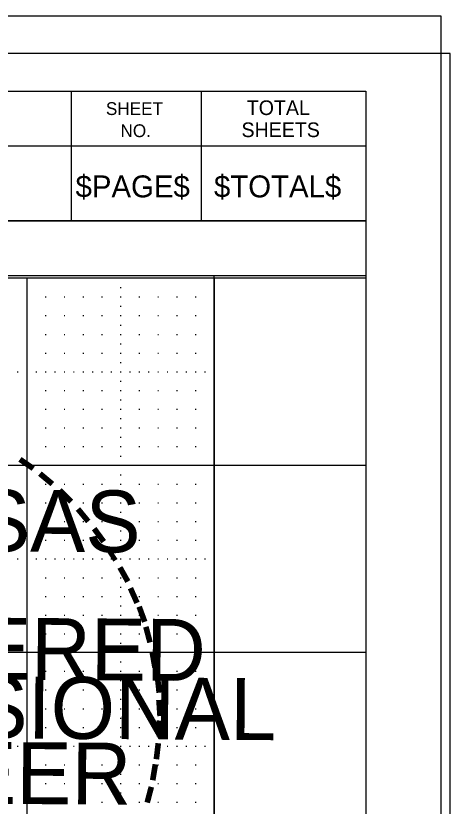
# Model space of a CAD drawing. Extents: x -3.6 to 32.1, y -0.4 to 25.6.
# Drawn here: x 29.748 to 32.067, y 16.724 to 20.947 of the extents above; entities that cross this region are included whole.
import ezdxf

# ---------------------------------------------------------------- set-up
doc = ezdxf.new("R2010")
doc.units = 0
for name, color, linetype in [('Level 1', 7, 'Continuous'), ('Level 4', 7, 'Continuous'), ('Level 5', 7, 'Continuous'), ('Level 62', 7, 'Continuous'), ('Level 63', 7, 'Continuous'), ('Level 63 Full', 7, 'Continuous'), ('R_Border Prelim', 7, 'Continuous'), ('R_Border Prem', 7, 'Continuous')]:
    doc.layers.add(name, color=color, linetype=linetype)

msp = doc.modelspace()

# ---------------------------------------------------------------- linework, layer by layer
at = {"layer": 'Level 1'}
for p, q in [((30.043, 20.5449), (30.043, 19.8509)), ((30.737, 20.5449), (30.737, 19.8509)), ((31.617, 20.2509), (27.307, 20.2509)), ((31.617, 20.2529), (31.617, 20.2529)), ((31.617, 19.8509), (27.307, 19.8509)), ((27.603, 19.8509), (31.617, 19.8509)), ((31.617, 19.5569), (25.353, 19.5569))]:
    msp.add_line(p, q, dxfattribs=at)
at = {"layer": 'Level 4'}
for p, q in [((31.617, 19.545), (-0.001, 19.545)), ((29.808, 0.545), (29.808, 19.545)), ((30.808, 0.545), (30.808, 19.545)), ((31.617, 18.545), (-0.001, 18.545)), ((31.617, 17.545), (-0.001, 17.545))]:
    msp.add_line(p, q, dxfattribs=at)
at = {"layer": 'Level 5'}
for p, q in [((30.3055, 19.495), (30.3105, 19.495)), ((29.9055, 19.445), (29.9105, 19.445)), ((30.0055, 19.445), (30.0105, 19.445)), ((30.1055, 19.445), (30.1105, 19.445)), ((30.2055, 19.445), (30.2105, 19.445)), ((30.3055, 19.445), (30.3105, 19.445)), ((30.4055, 19.445), (30.4105, 19.445)), ((30.5055, 19.445), (30.5105, 19.445)), ((30.6055, 19.445), (30.6105, 19.445)), ((30.7055, 19.445), (30.7105, 19.445)), ((30.3055, 19.395), (30.3105, 19.395)), ((29.9055, 19.345), (29.9105, 19.345)), ((30.0055, 19.345), (30.0105, 19.345)), ((30.1055, 19.345), (30.1105, 19.345)), ((30.2055, 19.345), (30.2105, 19.345)), ((30.3055, 19.345), (30.3105, 19.345)), ((30.4055, 19.345), (30.4105, 19.345)), ((30.5055, 19.345), (30.5105, 19.345)), ((30.6055, 19.345), (30.6105, 19.345)), ((30.7055, 19.345), (30.7105, 19.345)), ((30.3055, 19.295), (30.3105, 19.295)), ((29.9055, 19.245), (29.9105, 19.245)), ((30.0055, 19.245), (30.0105, 19.245)), ((30.1055, 19.245), (30.1105, 19.245)), ((30.2055, 19.245), (30.2105, 19.245)), ((30.3055, 19.245), (30.3105, 19.245)), ((30.4055, 19.245), (30.4105, 19.245)), ((30.5055, 19.245), (30.5105, 19.245)), ((30.6055, 19.245), (30.6105, 19.245)), ((30.7055, 19.245), (30.7105, 19.245)), ((30.3055, 19.195), (30.3105, 19.195)), ((29.9055, 19.145), (29.9105, 19.145)), ((30.0055, 19.145), (30.0105, 19.145)), ((30.1055, 19.145), (30.1105, 19.145)), ((30.2055, 19.145), (30.2105, 19.145)), ((30.3055, 19.145), (30.3105, 19.145)), ((30.4055, 19.145), (30.4105, 19.145)), ((30.5055, 19.145), (30.5105, 19.145)), ((30.6055, 19.145), (30.6105, 19.145)), ((30.7055, 19.145), (30.7105, 19.145)), ((30.3055, 19.095), (30.3105, 19.095)), ((29.7555, 19.045), (29.7605, 19.045)), ((29.8555, 19.045), (29.8605, 19.045)), ((29.9055, 19.045), (29.9105, 19.045)), ((29.9555, 19.045), (29.9605, 19.045)), ((30.0055, 19.045), (30.0105, 19.045)), ((30.0555, 19.045), (30.0605, 19.045)), ((30.1055, 19.045), (30.1105, 19.045)), ((30.1555, 19.045), (30.1605, 19.045)), ((30.2055, 19.045), (30.2105, 19.045)), ((30.2555, 19.045), (30.2605, 19.045)), ((30.3055, 19.045), (30.3105, 19.045)), ((30.3555, 19.045), (30.3605, 19.045)), ((30.4055, 19.045), (30.4105, 19.045)), ((30.4555, 19.045), (30.4605, 19.045)), ((30.5055, 19.045), (30.5105, 19.045)), ((30.5555, 19.045), (30.5605, 19.045)), ((30.6055, 19.045), (30.6105, 19.045)), ((30.6555, 19.045), (30.6605, 19.045)), ((30.7055, 19.045), (30.7105, 19.045)), ((30.7555, 19.045), (30.7605, 19.045)), ((30.3055, 18.995), (30.3105, 18.995)), ((29.9055, 18.945), (29.9105, 18.945)), ((30.0055, 18.945), (30.0105, 18.945)), ((30.1055, 18.945), (30.1105, 18.945)), ((30.2055, 18.945), (30.2105, 18.945)), ((30.3055, 18.945), (30.3105, 18.945)), ((30.4055, 18.945), (30.4105, 18.945)), ((30.5055, 18.945), (30.5105, 18.945)), ((30.6055, 18.945), (30.6105, 18.945)), ((30.7055, 18.945), (30.7105, 18.945)), ((30.3055, 18.895), (30.3105, 18.895)), ((29.9055, 18.845), (29.9105, 18.845)), ((30.0055, 18.845), (30.0105, 18.845)), ((30.1055, 18.845), (30.1105, 18.845)), ((30.2055, 18.845), (30.2105, 18.845)), ((30.3055, 18.845), (30.3105, 18.845)), ((30.4055, 18.845), (30.4105, 18.845)), ((30.5055, 18.845), (30.5105, 18.845)), ((30.6055, 18.845), (30.6105, 18.845)), ((30.7055, 18.845), (30.7105, 18.845)), ((30.3055, 18.795), (30.3105, 18.795)), ((29.9055, 18.745), (29.9105, 18.745)), ((30.0055, 18.745), (30.0105, 18.745)), ((30.1055, 18.745), (30.1105, 18.745)), ((30.2055, 18.745), (30.2105, 18.745)), ((30.3055, 18.745), (30.3105, 18.745)), ((30.4055, 18.745), (30.4105, 18.745)), ((30.5055, 18.745), (30.5105, 18.745)), ((30.6055, 18.745), (30.6105, 18.745)), ((30.7055, 18.745), (30.7105, 18.745)), ((30.3055, 18.695), (30.3105, 18.695)), ((29.9055, 18.645), (29.9105, 18.645)), ((30.0055, 18.645), (30.0105, 18.645)), ((30.1055, 18.645), (30.1105, 18.645)), ((30.2055, 18.645), (30.2105, 18.645)), ((30.3055, 18.645), (30.3105, 18.645)), ((30.4055, 18.645), (30.4105, 18.645)), ((30.5055, 18.645), (30.5105, 18.645)), ((30.6055, 18.645), (30.6105, 18.645)), ((30.7055, 18.645), (30.7105, 18.645)), ((30.3055, 18.595), (30.3105, 18.595)), ((30.3055, 18.495), (30.3105, 18.495)), ((29.9055, 18.445), (29.9105, 18.445)), ((30.0055, 18.445), (30.0105, 18.445)), ((30.1055, 18.445), (30.1105, 18.445)), ((30.2055, 18.445), (30.2105, 18.445)), ((30.3055, 18.445), (30.3105, 18.445)), ((30.4055, 18.445), (30.4105, 18.445)), ((30.5055, 18.445), (30.5105, 18.445)), ((30.6055, 18.445), (30.6105, 18.445)), ((30.7055, 18.445), (30.7105, 18.445)), ((30.3055, 18.395), (30.3105, 18.395)), ((29.9055, 18.345), (29.9105, 18.345)), ((30.0055, 18.345), (30.0105, 18.345)), ((30.1055, 18.345), (30.1105, 18.345)), ((30.2055, 18.345), (30.2105, 18.345)), ((30.3055, 18.345), (30.3105, 18.345)), ((30.4055, 18.345), (30.4105, 18.345)), ((30.5055, 18.345), (30.5105, 18.345)), ((30.6055, 18.345), (30.6105, 18.345)), ((30.7055, 18.345), (30.7105, 18.345)), ((30.3055, 18.295), (30.3105, 18.295)), ((29.9055, 18.245), (29.9105, 18.245)), ((30.0055, 18.245), (30.0105, 18.245)), ((30.1055, 18.245), (30.1105, 18.245)), ((30.2055, 18.245), (30.2105, 18.245)), ((30.3055, 18.245), (30.3105, 18.245)), ((30.4055, 18.245), (30.4105, 18.245)), ((30.5055, 18.245), (30.5105, 18.245)), ((30.6055, 18.245), (30.6105, 18.245)), ((30.7055, 18.245), (30.7105, 18.245)), ((30.3055, 18.195), (30.3105, 18.195)), ((29.9055, 18.145), (29.9105, 18.145)), ((30.0055, 18.145), (30.0105, 18.145)), ((30.1055, 18.145), (30.1105, 18.145)), ((30.2055, 18.145), (30.2105, 18.145)), ((30.3055, 18.145), (30.3105, 18.145)), ((30.4055, 18.145), (30.4105, 18.145)), ((30.5055, 18.145), (30.5105, 18.145)), ((30.6055, 18.145), (30.6105, 18.145)), ((30.7055, 18.145), (30.7105, 18.145)), ((30.3055, 18.095), (30.3105, 18.095)), ((29.7555, 18.045), (29.7605, 18.045)), ((29.8555, 18.045), (29.8605, 18.045)), ((29.9055, 18.045), (29.9105, 18.045)), ((29.9555, 18.045), (29.9605, 18.045)), ((30.0055, 18.045), (30.0105, 18.045)), ((30.0555, 18.045), (30.0605, 18.045)), ((30.1055, 18.045), (30.1105, 18.045)), ((30.1555, 18.045), (30.1605, 18.045)), ((30.2055, 18.045), (30.2105, 18.045)), ((30.2555, 18.045), (30.2605, 18.045)), ((30.3055, 18.045), (30.3105, 18.045)), ((30.3555, 18.045), (30.3605, 18.045)), ((30.4055, 18.045), (30.4105, 18.045)), ((30.4555, 18.045), (30.4605, 18.045)), ((30.5055, 18.045), (30.5105, 18.045)), ((30.5555, 18.045), (30.5605, 18.045)), ((30.6055, 18.045), (30.6105, 18.045)), ((30.6555, 18.045), (30.6605, 18.045)), ((30.7055, 18.045), (30.7105, 18.045)), ((30.7555, 18.045), (30.7605, 18.045)), ((30.3055, 17.995), (30.3105, 17.995)), ((29.9055, 17.945), (29.9105, 17.945)), ((30.0055, 17.945), (30.0105, 17.945)), ((30.1055, 17.945), (30.1105, 17.945)), ((30.2055, 17.945), (30.2105, 17.945)), ((30.3055, 17.945), (30.3105, 17.945)), ((30.4055, 17.945), (30.4105, 17.945)), ((30.5055, 17.945), (30.5105, 17.945)), ((30.6055, 17.945), (30.6105, 17.945)), ((30.7055, 17.945), (30.7105, 17.945)), ((30.3055, 17.895), (30.3105, 17.895)), ((29.9055, 17.845), (29.9105, 17.845)), ((30.0055, 17.845), (30.0105, 17.845)), ((30.1055, 17.845), (30.1105, 17.845)), ((30.2055, 17.845), (30.2105, 17.845)), ((30.3055, 17.845), (30.3105, 17.845)), ((30.4055, 17.845), (30.4105, 17.845)), ((30.5055, 17.845), (30.5105, 17.845)), ((30.6055, 17.845), (30.6105, 17.845)), ((30.7055, 17.845), (30.7105, 17.845)), ((30.3055, 17.795), (30.3105, 17.795)), ((29.9055, 17.745), (29.9105, 17.745)), ((30.0055, 17.745), (30.0105, 17.745)), ((30.1055, 17.745), (30.1105, 17.745)), ((30.2055, 17.745), (30.2105, 17.745)), ((30.3055, 17.745), (30.3105, 17.745)), ((30.4055, 17.745), (30.4105, 17.745)), ((30.5055, 17.745), (30.5105, 17.745)), ((30.6055, 17.745), (30.6105, 17.745)), ((30.7055, 17.745), (30.7105, 17.745)), ((30.3055, 17.695), (30.3105, 17.695)), ((29.9055, 17.645), (29.9105, 17.645)), ((30.0055, 17.645), (30.0105, 17.645)), ((30.1055, 17.645), (30.1105, 17.645)), ((30.2055, 17.645), (30.2105, 17.645)), ((30.3055, 17.645), (30.3105, 17.645)), ((30.4055, 17.645), (30.4105, 17.645)), ((30.5055, 17.645), (30.5105, 17.645)), ((30.6055, 17.645), (30.6105, 17.645)), ((30.7055, 17.645), (30.7105, 17.645)), ((30.3055, 17.595), (30.3105, 17.595)), ((30.3055, 17.495), (30.3105, 17.495)), ((29.9055, 17.445), (29.9105, 17.445)), ((30.0055, 17.445), (30.0105, 17.445)), ((30.1055, 17.445), (30.1105, 17.445)), ((30.2055, 17.445), (30.2105, 17.445)), ((30.3055, 17.445), (30.3105, 17.445)), ((30.4055, 17.445), (30.4105, 17.445)), ((30.5055, 17.445), (30.5105, 17.445)), ((30.6055, 17.445), (30.6105, 17.445)), ((30.7055, 17.445), (30.7105, 17.445)), ((30.3055, 17.395), (30.3105, 17.395)), ((29.9055, 17.345), (29.9105, 17.345)), ((30.0055, 17.345), (30.0105, 17.345)), ((30.1055, 17.345), (30.1105, 17.345)), ((30.2055, 17.345), (30.2105, 17.345)), ((30.3055, 17.345), (30.3105, 17.345)), ((30.4055, 17.345), (30.4105, 17.345)), ((30.5055, 17.345), (30.5105, 17.345)), ((30.6055, 17.345), (30.6105, 17.345)), ((30.7055, 17.345), (30.7105, 17.345)), ((30.3055, 17.295), (30.3105, 17.295)), ((29.9055, 17.245), (29.9105, 17.245)), ((30.0055, 17.245), (30.0105, 17.245)), ((30.1055, 17.245), (30.1105, 17.245)), ((30.2055, 17.245), (30.2105, 17.245)), ((30.3055, 17.245), (30.3105, 17.245)), ((30.4055, 17.245), (30.4105, 17.245)), ((30.5055, 17.245), (30.5105, 17.245)), ((30.6055, 17.245), (30.6105, 17.245)), ((30.7055, 17.245), (30.7105, 17.245)), ((30.3055, 17.195), (30.3105, 17.195)), ((29.9055, 17.145), (29.9105, 17.145)), ((30.0055, 17.145), (30.0105, 17.145)), ((30.1055, 17.145), (30.1105, 17.145)), ((30.2055, 17.145), (30.2105, 17.145)), ((30.3055, 17.145), (30.3105, 17.145)), ((30.4055, 17.145), (30.4105, 17.145)), ((30.5055, 17.145), (30.5105, 17.145)), ((30.6055, 17.145), (30.6105, 17.145)), ((30.7055, 17.145), (30.7105, 17.145)), ((30.3055, 17.095), (30.3105, 17.095)), ((29.7555, 17.045), (29.7605, 17.045)), ((29.8555, 17.045), (29.8605, 17.045)), ((29.9055, 17.045), (29.9105, 17.045)), ((29.9555, 17.045), (29.9605, 17.045)), ((30.0055, 17.045), (30.0105, 17.045)), ((30.0555, 17.045), (30.0605, 17.045)), ((30.1055, 17.045), (30.1105, 17.045)), ((30.1555, 17.045), (30.1605, 17.045)), ((30.2055, 17.045), (30.2105, 17.045)), ((30.2555, 17.045), (30.2605, 17.045)), ((30.3055, 17.045), (30.3105, 17.045)), ((30.3555, 17.045), (30.3605, 17.045)), ((30.4055, 17.045), (30.4105, 17.045)), ((30.4555, 17.045), (30.4605, 17.045)), ((30.5055, 17.045), (30.5105, 17.045)), ((30.5555, 17.045), (30.5605, 17.045)), ((30.6055, 17.045), (30.6105, 17.045)), ((30.6555, 17.045), (30.6605, 17.045)), ((30.7055, 17.045), (30.7105, 17.045)), ((30.7555, 17.045), (30.7605, 17.045)), ((30.3055, 16.995), (30.3105, 16.995)), ((29.9055, 16.945), (29.9105, 16.945)), ((30.0055, 16.945), (30.0105, 16.945)), ((30.1055, 16.945), (30.1105, 16.945)), ((30.2055, 16.945), (30.2105, 16.945)), ((30.3055, 16.945), (30.3105, 16.945)), ((30.4055, 16.945), (30.4105, 16.945)), ((30.5055, 16.945), (30.5105, 16.945)), ((30.6055, 16.945), (30.6105, 16.945)), ((30.7055, 16.945), (30.7105, 16.945)), ((30.3055, 16.895), (30.3105, 16.895)), ((29.9055, 16.845), (29.9105, 16.845)), ((30.0055, 16.845), (30.0105, 16.845)), ((30.1055, 16.845), (30.1105, 16.845)), ((30.2055, 16.845), (30.2105, 16.845)), ((30.3055, 16.845), (30.3105, 16.845)), ((30.4055, 16.845), (30.4105, 16.845)), ((30.5055, 16.845), (30.5105, 16.845)), ((30.6055, 16.845), (30.6105, 16.845)), ((30.7055, 16.845), (30.7105, 16.845)), ((30.3055, 16.795), (30.3105, 16.795)), ((29.9055, 16.745), (29.9105, 16.745)), ((30.0055, 16.745), (30.0105, 16.745)), ((30.1055, 16.745), (30.1105, 16.745)), ((30.2055, 16.745), (30.2105, 16.745)), ((30.3055, 16.745), (30.3105, 16.745)), ((30.4055, 16.745), (30.4105, 16.745)), ((30.5055, 16.745), (30.5105, 16.745)), ((30.6055, 16.745), (30.6105, 16.745)), ((30.7055, 16.745), (30.7105, 16.745))]:
    msp.add_line(p, q, dxfattribs=at)
at = {"layer": 'Level 62'}
for p, q in [((30.8075, 19.5579), (26.9998, 19.558)), ((30.808, 0.545), (30.8075, 19.5579))]:
    msp.add_line(p, q, dxfattribs=at)
at = {"layer": 'Level 63'}
msp.add_lwpolyline([(-1.263, -0.2005), (32.067, -0.2005), (32.067, 20.7465), (-1.263, 20.7465)], close=True, dxfattribs=at)
at = {"layer": 'Level 63 Full'}
msp.add_lwpolyline([(32.017, -0.403), (-3.583, -0.403), (-3.583, 20.947), (32.017, 20.947)], close=True, dxfattribs=at)
at = {"layer": 'R_Border Prem'}
for p, q in [((-0.001, 20.545), (31.617, 20.545)), ((31.617, 20.545), (31.617, -0.001))]:
    msp.add_line(p, q, dxfattribs=at)

# ---------------------------------------------------------------- texts
at = {"layer": 'Level 1'}
for s, height, p in [('SHEET', 0.0684, (30.229, 20.4169)), ('TOTAL', 0.07819, (30.981, 20.4169)), ('NO.', 0.0684, (30.307, 20.2989)), ('SHEETS', 0.07819, (30.953, 20.2989)), ('$PAGE$', 0.11724, (30.067, 19.9769)), ('$TOTAL$', 0.11724, (30.806, 19.9769))]:
    msp.add_text(s, height=height, dxfattribs=at).set_placement(p)
at = {"layer": 'R_Border Prelim'}
for s, height, rotation, p in [('-', 0.2644, 325.4651, (29.6994, 18.502)), ('-', 0.2644, 320.1321, (29.7993, 18.4326)), ('ARKANSAS', 0.33055, 359.6024, (28.0062, 18.096)), ('-', 0.2644, 315.181, (29.8993, 18.351)), ('-', 0.2644, 309.4821, (29.9911, 18.2592)), ('-', 0.2644, 306.2546, (30.0747, 18.1593)), ('-', 0.2314, 303.2777, (30.1563, 18.0634)), ('-', 0.2644, 299.2708, (30.2073, 17.9634)), ('-', 0.2644, 294.2652, (30.2604, 17.8614)), ('-', 0.2644, 290.1752, (30.3053, 17.7696)), ('REGISTERED', 0.33055, 359.6024, (27.8879, 17.4126)), ('-', 0.2644, 284.7257, (30.3399, 17.6717)), ('-', 0.2644, 280.1517, (30.3726, 17.5473)), ('PROFESSIONAL', 0.330553, 359.6024, (27.6981, 17.1005)), ('-', 0.2644, 276.1986, (30.4011, 17.4208)), ('-', 0.2644, 273.9325, (30.4093, 17.3004)), ('-', 0.2644, 269.5431, (30.4134, 17.1984)), ('ENGINEER', 0.33055, 359.6024, (28.0551, 16.7476)), ('-', 0.2644, 263.1196, (30.4093, 17.0883)), ('-', 0.2644, 260.5977, (30.395, 16.9802)), ('-', 0.2644, 255.365, (30.3767, 16.868))]:
    msp.add_text(s, height=height, rotation=rotation, dxfattribs=at).set_placement(p)

doc.saveas('drawing.dxf')
